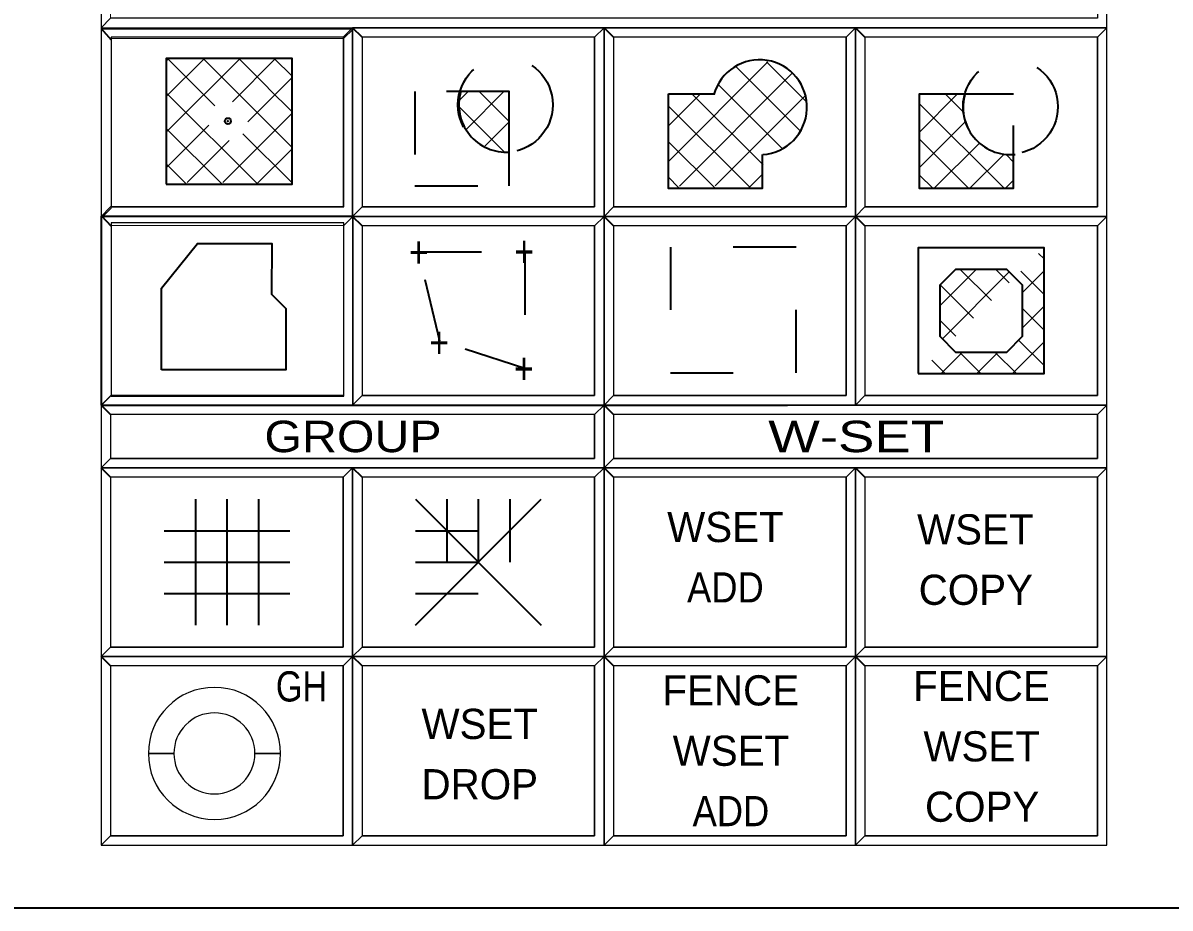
# Model space of a CAD drawing. Extents: x 95906.9 to 95918.9, y 90964.8 to 90972.9.
# Drawn here: x 95910.707 to 95912.532, y 90964.762 to 90966.169 of the extents above; entities that cross this region are included whole.
import ezdxf
from ezdxf.enums import TextEntityAlignment as Align

# ---------------------------------------------------------------- set-up
doc = ezdxf.new("R2010")
doc.units = 0
doc.header["$LTSCALE"] = 0.019
doc.header["$PDMODE"] = 32
doc.header["$PDSIZE"] = 0.0095
doc.linetypes.add('DOTTED', pattern=[1.5, 0.3, -1.2])
doc.linetypes.add('MEDIUM_DASHED', pattern=[4.5, 3, -1.5])
for name, color, linetype, lineweight in [('1', 7, 'Continuous', 25), ('11', 7, 'Continuous', 25), ('12', 7, 'Continuous', 25), ('16', 7, 'Continuous', 25), ('2', 7, 'Continuous', 13), ('3', 7, 'Continuous', 25), ('4', 7, 'Continuous', 35), ('6', 7, 'Continuous', 35), ('7', 7, 'Continuous', 35)]:
    doc.layers.add(name, color=color, linetype=linetype, lineweight=lineweight)

msp = doc.modelspace()

# ---------------------------------------------------------------- linework, layer by layer
at = {"layer": '1'}
msp.add_line((95910.8316, 90966.1619), (95910.8316, 90965.858), dxfattribs=at)
for points in [[(95910.8318, 90966.1617), (95912.4318, 90966.1617), (95912.4318, 90966.2617), (95910.8318, 90966.2617)], [(95911.2318, 90965.8617), (95911.6318, 90965.8617), (95911.6318, 90966.1617), (95911.2318, 90966.1617)], [(95911.6318, 90965.8617), (95912.0318, 90965.8617), (95912.0318, 90966.1617), (95911.6318, 90966.1617)], [(95912.0318, 90965.8617), (95912.4318, 90965.8617), (95912.4318, 90966.1617), (95912.0318, 90966.1617)], [(95911.2318, 90965.5617), (95911.6318, 90965.5617), (95911.6318, 90965.8617), (95911.2318, 90965.8617)], [(95911.6318, 90965.5617), (95912.0318, 90965.5617), (95912.0318, 90965.8617), (95911.6318, 90965.8617)], [(95912.0318, 90965.5617), (95912.4318, 90965.5617), (95912.4318, 90965.8617), (95912.0318, 90965.8617)], [(95910.8318, 90965.4617), (95911.6318, 90965.4617), (95911.6318, 90965.5617), (95910.8318, 90965.5617)], [(95911.6318, 90965.4617), (95912.4318, 90965.4617), (95912.4318, 90965.5617), (95911.6318, 90965.5617)], [(95910.8318, 90965.1617), (95911.2318, 90965.1617), (95911.2318, 90965.4617), (95910.8318, 90965.4617)], [(95911.2318, 90965.1617), (95911.6318, 90965.1617), (95911.6318, 90965.4617), (95911.2318, 90965.4617)], [(95911.6318, 90965.1617), (95912.0318, 90965.1617), (95912.0318, 90965.4617), (95911.6318, 90965.4617)], [(95912.0318, 90965.1617), (95912.4318, 90965.1617), (95912.4318, 90965.4617), (95912.0318, 90965.4617)], [(95910.8318, 90964.8617), (95911.2318, 90964.8617), (95911.2318, 90965.1617), (95910.8318, 90965.1617)], [(95911.2318, 90964.8617), (95911.6318, 90964.8617), (95911.6318, 90965.1617), (95911.2318, 90965.1617)], [(95911.6318, 90964.8617), (95912.0318, 90964.8617), (95912.0318, 90965.1617), (95911.6318, 90965.1617)], [(95912.0318, 90964.8617), (95912.4318, 90964.8617), (95912.4318, 90965.1617), (95912.0318, 90965.1617)]]:
    msp.add_lwpolyline(points, close=True, dxfattribs=at)
msp.add_lwpolyline([(95911.2314, 90965.8618), (95910.8314, 90965.8618), (95910.8314, 90965.5618), (95911.2314, 90965.5618), (95911.2314, 90965.562)], dxfattribs=at)
at = {"layer": '11'}
for points in [[(95910.8477, 90965.8767), (95911.2177, 90965.8767), (95911.2177, 90966.1467), (95910.8477, 90966.1467)], [(95911.2468, 90965.8767), (95911.6168, 90965.8767), (95911.6168, 90966.1467), (95911.2468, 90966.1467)], [(95911.6468, 90965.8767), (95912.0168, 90965.8767), (95912.0168, 90966.1467), (95911.6468, 90966.1467)], [(95912.0468, 90965.8767), (95912.4168, 90965.8767), (95912.4168, 90966.1467), (95912.0468, 90966.1467)], [(95910.8477, 90965.5759), (95911.2179, 90965.5759), (95911.2179, 90965.8513), (95910.8477, 90965.8513)], [(95911.2468, 90965.5767), (95911.6168, 90965.5767), (95911.6168, 90965.8467), (95911.2468, 90965.8467)], [(95911.6468, 90965.5767), (95912.0168, 90965.5767), (95912.0168, 90965.8467), (95911.6468, 90965.8467)], [(95912.0468, 90965.5767), (95912.4168, 90965.5767), (95912.4168, 90965.8467), (95912.0468, 90965.8467)], [(95910.8468, 90965.1767), (95911.2168, 90965.1767), (95911.2168, 90965.4467), (95910.8468, 90965.4467)], [(95911.2468, 90965.1767), (95911.6168, 90965.1767), (95911.6168, 90965.4467), (95911.2468, 90965.4467)], [(95911.6468, 90965.1767), (95912.0168, 90965.1767), (95912.0168, 90965.4467), (95911.6468, 90965.4467)], [(95912.0468, 90965.1767), (95912.4168, 90965.1767), (95912.4168, 90965.4467), (95912.0468, 90965.4467)], [(95910.8468, 90964.8767), (95911.2168, 90964.8767), (95911.2168, 90965.1467), (95910.8468, 90965.1467)], [(95911.2468, 90964.8767), (95911.6168, 90964.8767), (95911.6168, 90965.1467), (95911.2468, 90965.1467)], [(95911.6468, 90964.8767), (95912.0168, 90964.8767), (95912.0168, 90965.1467), (95911.6468, 90965.1467)], [(95912.0468, 90964.8767), (95912.4168, 90964.8767), (95912.4168, 90965.1467), (95912.0468, 90965.1467)]]:
    msp.add_lwpolyline(points, close=True, dxfattribs=at)
at = {"layer": '12'}
msp.add_lwpolyline([(95910.8468, 90965.1767), (95911.2168, 90965.1767), (95911.2168, 90965.4467), (95910.8468, 90965.4467)], close=True, dxfattribs=at)
at = {"layer": '16'}
for points in [[(95910.8468, 90965.4767), (95911.6168, 90965.4767), (95911.6168, 90965.5467), (95910.8468, 90965.5467)], [(95911.6468, 90965.4767), (95912.4168, 90965.4767), (95912.4168, 90965.5467), (95911.6468, 90965.5467)]]:
    msp.add_lwpolyline(points, close=True, dxfattribs=at)
at = {"layer": '2'}
for points in [[(95910.8318, 90966.2617), (95910.8318, 90966.1617), (95910.8468, 90966.1767), (95910.8468, 90966.2467), (95912.4168, 90966.2467), (95912.4318, 90966.2617)], [(95910.8325, 90966.1596), (95910.8325, 90965.8596), (95910.8475, 90965.8746), (95910.8475, 90966.1446), (95911.2175, 90966.1446), (95911.2325, 90966.1596)], [(95911.2318, 90966.1617), (95911.2318, 90965.8617), (95911.2468, 90965.8767), (95911.2468, 90966.1467), (95911.6168, 90966.1467), (95911.6318, 90966.1617)], [(95911.6318, 90966.1617), (95911.6318, 90965.8617), (95911.6468, 90965.8767), (95911.6468, 90966.1467), (95912.0168, 90966.1467), (95912.0318, 90966.1617)], [(95912.0318, 90966.1617), (95912.0318, 90965.8617), (95912.0468, 90965.8767), (95912.0468, 90966.1467), (95912.4168, 90966.1467), (95912.4318, 90966.1617)], [(95910.8329, 90965.8621), (95910.8329, 90965.5621), (95910.8479, 90965.5771), (95910.8479, 90965.8471), (95911.2179, 90965.8471), (95911.2329, 90965.8621)], [(95911.2318, 90965.8617), (95911.2318, 90965.5617), (95911.2468, 90965.5767), (95911.2468, 90965.8467), (95911.6168, 90965.8467), (95911.6318, 90965.8617)], [(95911.6318, 90965.8617), (95911.6318, 90965.5617), (95911.6468, 90965.5767), (95911.6468, 90965.8467), (95912.0168, 90965.8467), (95912.0318, 90965.8617)], [(95912.0318, 90965.8617), (95912.0318, 90965.5617), (95912.0468, 90965.5767), (95912.0468, 90965.8467), (95912.4168, 90965.8467), (95912.4318, 90965.8617)], [(95910.8318, 90965.5617), (95910.8318, 90965.4617), (95910.8468, 90965.4767), (95910.8468, 90965.5467), (95911.6168, 90965.5467), (95911.6318, 90965.5617)], [(95911.6318, 90965.5617), (95911.6318, 90965.4617), (95911.6468, 90965.4767), (95911.6468, 90965.5467), (95912.4168, 90965.5467), (95912.4318, 90965.5617)], [(95910.8318, 90965.4617), (95910.8318, 90965.1617), (95910.8468, 90965.1767), (95910.8468, 90965.4467), (95911.2168, 90965.4467), (95911.2318, 90965.4617)], [(95911.2318, 90965.4617), (95911.2318, 90965.1617), (95911.2468, 90965.1767), (95911.2468, 90965.4467), (95911.6168, 90965.4467), (95911.6318, 90965.4617)], [(95911.6318, 90965.4617), (95911.6318, 90965.1617), (95911.6468, 90965.1767), (95911.6468, 90965.4467), (95912.0168, 90965.4467), (95912.0318, 90965.4617)], [(95912.0318, 90965.4617), (95912.0318, 90965.1617), (95912.0468, 90965.1767), (95912.0468, 90965.4467), (95912.4168, 90965.4467), (95912.4318, 90965.4617)], [(95910.8318, 90965.1617), (95910.8318, 90964.8617), (95910.8468, 90964.8767), (95910.8468, 90965.1467), (95911.2168, 90965.1467), (95911.2318, 90965.1617)], [(95911.2318, 90965.1617), (95911.2318, 90964.8617), (95911.2468, 90964.8767), (95911.2468, 90965.1467), (95911.6168, 90965.1467), (95911.6318, 90965.1617)], [(95911.6318, 90965.1617), (95911.6318, 90964.8617), (95911.6468, 90964.8767), (95911.6468, 90965.1467), (95912.0168, 90965.1467), (95912.0318, 90965.1617)], [(95912.0318, 90965.1617), (95912.0318, 90964.8617), (95912.0468, 90964.8767), (95912.0468, 90965.1467), (95912.4168, 90965.1467), (95912.4318, 90965.1617)]]:
    msp.add_lwpolyline(points, close=True, dxfattribs=at)
at = {"layer": '3'}
for points in [[(95910.8318, 90966.1617), (95912.4318, 90966.1617), (95912.4318, 90966.2617), (95912.4168, 90966.2467), (95912.4168, 90966.1767), (95910.8468, 90966.1767)], [(95910.8318, 90965.8617), (95911.2318, 90965.8617), (95911.2318, 90966.1617), (95911.2168, 90966.1467), (95911.2168, 90965.8767), (95910.8468, 90965.8767)], [(95911.2318, 90965.8617), (95911.6318, 90965.8617), (95911.6318, 90966.1617), (95911.6168, 90966.1467), (95911.6168, 90965.8767), (95911.2468, 90965.8767)], [(95911.6318, 90965.8617), (95912.0318, 90965.8617), (95912.0318, 90966.1617), (95912.0168, 90966.1467), (95912.0168, 90965.8767), (95911.6468, 90965.8767)], [(95912.0318, 90965.8617), (95912.4318, 90965.8617), (95912.4318, 90966.1617), (95912.4168, 90966.1467), (95912.4168, 90965.8767), (95912.0468, 90965.8767)], [(95910.8325, 90965.5618), (95911.2325, 90965.5618), (95911.2325, 90965.8618), (95911.2175, 90965.8468), (95911.2175, 90965.5768), (95910.8475, 90965.5768)], [(95911.2318, 90965.5617), (95911.6318, 90965.5617), (95911.6318, 90965.8617), (95911.6168, 90965.8467), (95911.6168, 90965.5767), (95911.2468, 90965.5767)], [(95911.6318, 90965.5617), (95912.0318, 90965.5617), (95912.0318, 90965.8617), (95912.0168, 90965.8467), (95912.0168, 90965.5767), (95911.6468, 90965.5767)], [(95912.0318, 90965.5617), (95912.4318, 90965.5617), (95912.4318, 90965.8617), (95912.4168, 90965.8467), (95912.4168, 90965.5767), (95912.0468, 90965.5767)], [(95910.8318, 90965.4617), (95911.6318, 90965.4617), (95911.6318, 90965.5617), (95911.6168, 90965.5467), (95911.6168, 90965.4767), (95910.8468, 90965.4767)], [(95911.6318, 90965.4617), (95912.4318, 90965.4617), (95912.4318, 90965.5617), (95912.4168, 90965.5467), (95912.4168, 90965.4767), (95911.6468, 90965.4767)], [(95910.8318, 90965.1617), (95911.2318, 90965.1617), (95911.2318, 90965.4617), (95911.2168, 90965.4467), (95911.2168, 90965.1767), (95910.8468, 90965.1767)], [(95911.2318, 90965.1617), (95911.6318, 90965.1617), (95911.6318, 90965.4617), (95911.6168, 90965.4467), (95911.6168, 90965.1767), (95911.2468, 90965.1767)], [(95911.6318, 90965.1617), (95912.0318, 90965.1617), (95912.0318, 90965.4617), (95912.0168, 90965.4467), (95912.0168, 90965.1767), (95911.6468, 90965.1767)], [(95912.0318, 90965.1617), (95912.4318, 90965.1617), (95912.4318, 90965.4617), (95912.4168, 90965.4467), (95912.4168, 90965.1767), (95912.0468, 90965.1767)], [(95910.8318, 90964.8617), (95911.2318, 90964.8617), (95911.2318, 90965.1617), (95911.2168, 90965.1467), (95911.2168, 90964.8767), (95910.8468, 90964.8767)], [(95911.2318, 90964.8617), (95911.6318, 90964.8617), (95911.6318, 90965.1617), (95911.6168, 90965.1467), (95911.6168, 90964.8767), (95911.2468, 90964.8767)], [(95911.6318, 90964.8617), (95912.0318, 90964.8617), (95912.0318, 90965.1617), (95912.0168, 90965.1467), (95912.0168, 90964.8767), (95911.6468, 90964.8767)], [(95912.0318, 90964.8617), (95912.4318, 90964.8617), (95912.4318, 90965.1617), (95912.4168, 90965.1467), (95912.4168, 90964.8767), (95912.0468, 90964.8767)]]:
    msp.add_lwpolyline(points, close=True, dxfattribs=at)
at = {"layer": '4'}
for p, q in [((95910.8316, 90966.1605), (95910.8478, 90966.1423)), ((95911.2468, 90966.1467), (95911.2318, 90966.1617)), ((95911.6468, 90966.1467), (95911.6318, 90966.1617)), ((95912.0468, 90966.1467), (95912.0318, 90966.1617)), ((95910.8325, 90965.8624), (95910.8478, 90965.8461)), ((95911.2468, 90965.8467), (95911.2318, 90965.8617)), ((95911.6468, 90965.8467), (95911.6318, 90965.8617)), ((95912.0468, 90965.8467), (95912.0318, 90965.8617)), ((95910.8468, 90965.5467), (95910.8318, 90965.5617)), ((95911.6468, 90965.5467), (95911.6318, 90965.5617)), ((95910.8468, 90965.4467), (95910.8318, 90965.4617)), ((95911.2468, 90965.4467), (95911.2318, 90965.4617)), ((95911.6468, 90965.4467), (95911.6318, 90965.4617)), ((95912.0468, 90965.4467), (95912.0318, 90965.4617)), ((95910.8468, 90965.1467), (95910.8318, 90965.1617)), ((95911.2468, 90965.1467), (95911.2318, 90965.1617)), ((95911.6468, 90965.1467), (95911.6318, 90965.1617)), ((95912.0468, 90965.1467), (95912.0318, 90965.1617))]:
    msp.add_line(p, q, dxfattribs=at)
at = {"layer": '6', "lineweight": 13}
for p, q in [((95910.8318, 90965.8617), (95910.8318, 90966.1617)), ((95910.9354, 90965.9955), (95911.0527, 90966.1128)), ((95910.9354, 90966.0521), (95910.9961, 90966.1128)), ((95910.9354, 90966.1087), (95910.9395, 90966.1128)), ((95910.9374, 90966.1128), (95911.0128, 90966.0375)), ((95910.994, 90966.1128), (95911.1355, 90965.9713)), ((95911.0405, 90966.0441), (95911.1092, 90966.1128)), ((95911.0506, 90966.1128), (95911.0972, 90966.0662)), ((95911.1071, 90966.1128), (95911.1354, 90966.0845)), ((95911.7341, 90965.9489), (95911.8925, 90966.1073)), ((95911.8904, 90966.1073), (95911.9539, 90966.0438)), ((95911.7517, 90965.9099), (95911.9306, 90966.0887)), ((95911.8407, 90966.1005), (95911.8805, 90966.0607)), ((95911.0652, 90966.0123), (95911.1354, 90966.0824)), ((95911.8144, 90966.0703), (95911.9152, 90965.9695)), ((95910.9354, 90966.0583), (95911.0797, 90965.914)), ((95911.0977, 90966.0657), (95911.1354, 90966.028)), ((95911.3994, 90966.0439), (95911.4157, 90966.0601)), ((95911.4122, 90966), (95911.4723, 90966.0602)), ((95911.4343, 90966.0592), (95911.4812, 90966.0123)), ((95911.7338, 90966.0051), (95911.7845, 90966.0558)), ((95911.772, 90966.0562), (95911.8847, 90965.9437)), ((95911.8084, 90965.91), (95911.9529, 90966.0545)), ((95911.881, 90966.0602), (95911.9442, 90965.997)), ((95912.134, 90965.9963), (95912.1932, 90966.0555)), ((95912.1751, 90966.056), (95912.2038, 90966.0273)), ((95911.4011, 90966.0359), (95911.4727, 90965.9644)), ((95911.7354, 90966.0361), (95911.863, 90965.9085)), ((95912.1334, 90966.0411), (95912.2682, 90965.9063)), ((95911.0251, 90965.9155), (95911.1354, 90966.0258)), ((95911.4404, 90965.9717), (95911.481, 90966.0123)), ((95912.133, 90965.9387), (95912.2067, 90966.0124)), ((95910.9354, 90965.939), (95911.003, 90966.0066)), ((95910.9354, 90966.0017), (95911.0252, 90965.9119)), ((95910.9684, 90965.9154), (95911.0353, 90965.9823)), ((95911.0571, 90965.9931), (95911.1349, 90965.9153)), ((95911.7355, 90965.9794), (95911.8085, 90965.9064)), ((95912.1329, 90965.985), (95912.2116, 90965.9063)), ((95912.1577, 90965.9069), (95912.2284, 90965.9777)), ((95911.0789, 90965.9128), (95911.1354, 90965.9693)), ((95912.2144, 90965.907), (95912.2666, 90965.9591)), ((95912.2713, 90965.96), (95912.284, 90965.9473)), ((95910.9354, 90965.9451), (95910.9677, 90965.9128)), ((95911.7336, 90965.9247), (95911.751, 90965.9073)), ((95911.8622, 90965.9073), (95911.8842, 90965.9293)), ((95912.1333, 90965.928), (95912.1552, 90965.9061)), ((95912.27, 90965.9061), (95912.2834, 90965.9195)), ((95912.3229, 90965.8028), (95912.3318, 90965.794)), ((95912.1661, 90965.7195), (95912.224, 90965.7774)), ((95912.1984, 90965.7774), (95912.248, 90965.7279)), ((95912.255, 90965.7774), (95912.2762, 90965.7561)), ((95912.2947, 90965.7746), (95912.3318, 90965.7374)), ((95912.3318, 90965.7752), (95912.2979, 90965.7413)), ((95912.1701, 90965.667), (95912.2765, 90965.7734)), ((95912.1665, 90965.7528), (95912.2197, 90965.6996)), ((95912.3318, 90965.6808), (95912.2968, 90965.7158)), ((95912.3318, 90965.7187), (95912.2978, 90965.6847)), ((95912.1661, 90965.6966), (95912.1914, 90965.6713)), ((95912.3318, 90965.6243), (95912.2907, 90965.6653)), ((95912.2814, 90965.6117), (95912.3318, 90965.6621)), ((95912.1532, 90965.6331), (95912.1747, 90965.6117)), ((95912.1683, 90965.6117), (95912.1989, 90965.6423)), ((95912.2312, 90965.6117), (95912.1974, 90965.6455)), ((95912.2248, 90965.6117), (95912.2584, 90965.6453)), ((95912.2878, 90965.6117), (95912.2548, 90965.6447))]:
    msp.add_line(p, q, dxfattribs=at)
at = {"layer": '6'}
for p, q in [((95911.8074, 90966.0563), (95911.7343, 90966.0563)), ((95910.8318, 90965.5617), (95911.9238, 90965.5617)), ((95910.9818, 90965.4117), (95910.9818, 90965.2117)), ((95911.0318, 90965.4117), (95911.0318, 90965.2117)), ((95911.0818, 90965.4117), (95911.0818, 90965.2117)), ((95911.3318, 90965.2117), (95911.5318, 90965.4117)), ((95911.3318, 90965.4117), (95911.5318, 90965.2117)), ((95910.9318, 90965.3617), (95911.1318, 90965.3617)), ((95910.9318, 90965.3117), (95911.1318, 90965.3117)), ((95910.9318, 90965.2617), (95911.1318, 90965.2617))]:
    msp.add_line(p, q, dxfattribs=at)
at = {"layer": '6', "linetype": 'MEDIUM_DASHED'}
for p, q in [((95911.3818, 90965.4117), (95911.3818, 90965.2117)), ((95911.4318, 90965.4117), (95911.4318, 90965.2117)), ((95911.4818, 90965.4117), (95911.4818, 90965.2117)), ((95911.3318, 90965.3617), (95911.5318, 90965.3617)), ((95911.3318, 90965.3117), (95911.5318, 90965.3117)), ((95911.3318, 90965.2617), (95911.5318, 90965.2617))]:
    msp.add_line(p, q, dxfattribs=at)
at = {"layer": '6', "lineweight": 25}
for p, q in [((95910.9068, 90965.0076), (95910.9475, 90965.0076)), ((95910.9475, 90965.0076), (95910.9068, 90965.0076)), ((95911.0763, 90965.0076), (95911.117, 90965.0076)), ((95911.117, 90965.0076), (95911.0763, 90965.0076))]:
    msp.add_line(p, q, dxfattribs=at)
at = {"layer": '6'}
for points in [[(95910.9354, 90965.9128), (95911.1354, 90965.9128), (95911.1354, 90966.1128), (95910.9354, 90966.1128)], [(95910.9279, 90965.6175), (95910.9279, 90965.7476), (95910.9848, 90965.8186), (95911.0827, 90965.8186), (95911.1031, 90965.8186), (95911.1027, 90965.738), (95911.1254, 90965.7153), (95911.1254, 90965.6175)], [(95912.1318, 90965.6117), (95912.3318, 90965.6117), (95912.3318, 90965.8117), (95912.1318, 90965.8117)], [(95912.1911, 90965.646), (95912.2725, 90965.646), (95912.2975, 90965.671), (95912.2975, 90965.7524), (95912.2725, 90965.7774), (95912.1911, 90965.7774), (95912.1661, 90965.7524), (95912.1661, 90965.671)]]:
    msp.add_lwpolyline(points, close=True, dxfattribs=at)
at = {"layer": '6', "linetype": 'DOTTED'}
for points in [[(95911.3309, 90965.9101), (95911.4809, 90965.9101), (95911.4809, 90966.0601), (95911.3309, 90966.0601)], [(95912.133, 90965.9063), (95912.283, 90965.9063), (95912.283, 90966.0563), (95912.133, 90966.0563)], [(95911.7374, 90965.6128), (95911.9374, 90965.6128), (95911.9374, 90965.8128), (95911.7374, 90965.8128)]]:
    msp.add_lwpolyline(points, close=True, dxfattribs=at)
at = {"layer": '6'}
for points in [[(95911.4809, 90965.9594), (95911.4809, 90966.0601), (95911.4057, 90966.0601)], [(95911.7339, 90966.0566), (95911.7339, 90965.9063), (95911.8839, 90965.9063), (95911.8839, 90965.9601)], [(95912.2079, 90966.0563), (95912.133, 90966.0563), (95912.133, 90965.9063), (95912.283, 90965.9063), (95912.283, 90965.9622)]]:
    msp.add_lwpolyline(points, dxfattribs=at)
at = {"layer": '6', "linetype": 'MEDIUM_DASHED'}
msp.add_lwpolyline([(95911.337, 90965.8051), (95911.5058, 90965.8051), (95911.5058, 90965.6197), (95911.3704, 90965.6634)], close=True, dxfattribs=at)
at = {"layer": '6', "linetype": 'DOTTED'}
for centre in [(95911.4748, 90966.0391), (95912.2784, 90966.0362)]:
    msp.add_circle(centre, 0.0754, dxfattribs=at)
at = {"layer": '6'}
for centre, start, end in [((95911.8793, 90966.0353), 273.8644, 164.6109), ((95911.4763, 90966.0391), 163.6588, 274.1636), ((95912.2784, 90966.0353), 162.9658, 275.5202)]:
    msp.add_arc(centre, 0.0754, start, end, dxfattribs=at)
at = {"layer": '6', "lineweight": 25}
for centre, radius, start, end in [((95911.012, 90965.0075), 0.1052, 90.0315, 179.9685), ((95911.0118, 90965.0075), 0.1052, 0.0315, 89.9685), ((95911.0117, 90965.0078), 0.0642, 89.8108, 180.1892), ((95911.0121, 90965.0078), 0.0642, 359.8108, 90.1892), ((95911.012, 90965.0077), 0.1052, 180.0315, 269.9685), ((95911.0117, 90965.0074), 0.0642, 179.8108, 270.1892), ((95911.0118, 90965.0077), 0.1052, 270.0315, 359.9685), ((95911.0121, 90965.0074), 0.0642, 269.8108, 0.1892)]:
    msp.add_arc(centre, radius, start, end, dxfattribs=at)
at = {"layer": '6'}
msp.add_point((95911.0334, 90966.0133), dxfattribs=at)
at = {"layer": '7'}
msp.add_lwpolyline([(95906.8548, 90972.8617), (95918.8548, 90972.8617), (95918.8548, 90964.7617), (95906.8548, 90964.7617)], close=True, dxfattribs=at)

# ---------------------------------------------------------------- texts
at = {"layer": '6', "width": 0.8}
for p in [(95911.3213, 90965.7801), (95911.4893, 90965.781), (95911.3537, 90965.6364), (95911.4888, 90965.5949)]:
    msp.add_text('+', height=0.05, dxfattribs=at).set_placement(p)
at = {"layer": '6'}
for s, p in [('WSET', (95911.8249, 90965.3437)), ('WSET', (95912.2225, 90965.3399)), ('COPY', (95912.2233, 90965.2439)), ('FENCE', (95912.2323, 90965.0909)), ('FENCE', (95911.8334, 90965.0839)), ('WSET', (95911.4341, 90965.0306)), ('WSET', (95911.8337, 90964.9879)), ('WSET', (95912.2326, 90964.9949)), ('DROP', (95911.4341, 90964.9346)), ('COPY', (95912.2334, 90964.8989))]:
    msp.add_text(s, height=0.048, dxfattribs=at).set_placement(p, align=Align.CENTER)
for s, width, p in [('ADD', 0.9, (95911.8249, 90965.2477)), ('GH', 0.85, (95911.1505, 90965.0902)), ('ADD', 0.9, (95911.8337, 90964.8919))]:
    msp.add_text(s, height=0.048, dxfattribs=dict(at, width=width)).set_placement(p, align=Align.CENTER)
at = {"layer": '7'}
for s, width, p in [('GROUP', 1.15, (95911.2324, 90965.4867)), ('W-SET', 1.3, (95912.033, 90965.4867))]:
    msp.add_text(s, height=0.04999, dxfattribs=dict(at, width=width)).set_placement(p, align=Align.CENTER)

doc.saveas('drawing.dxf')
